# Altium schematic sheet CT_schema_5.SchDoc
size 369 x 245 mm
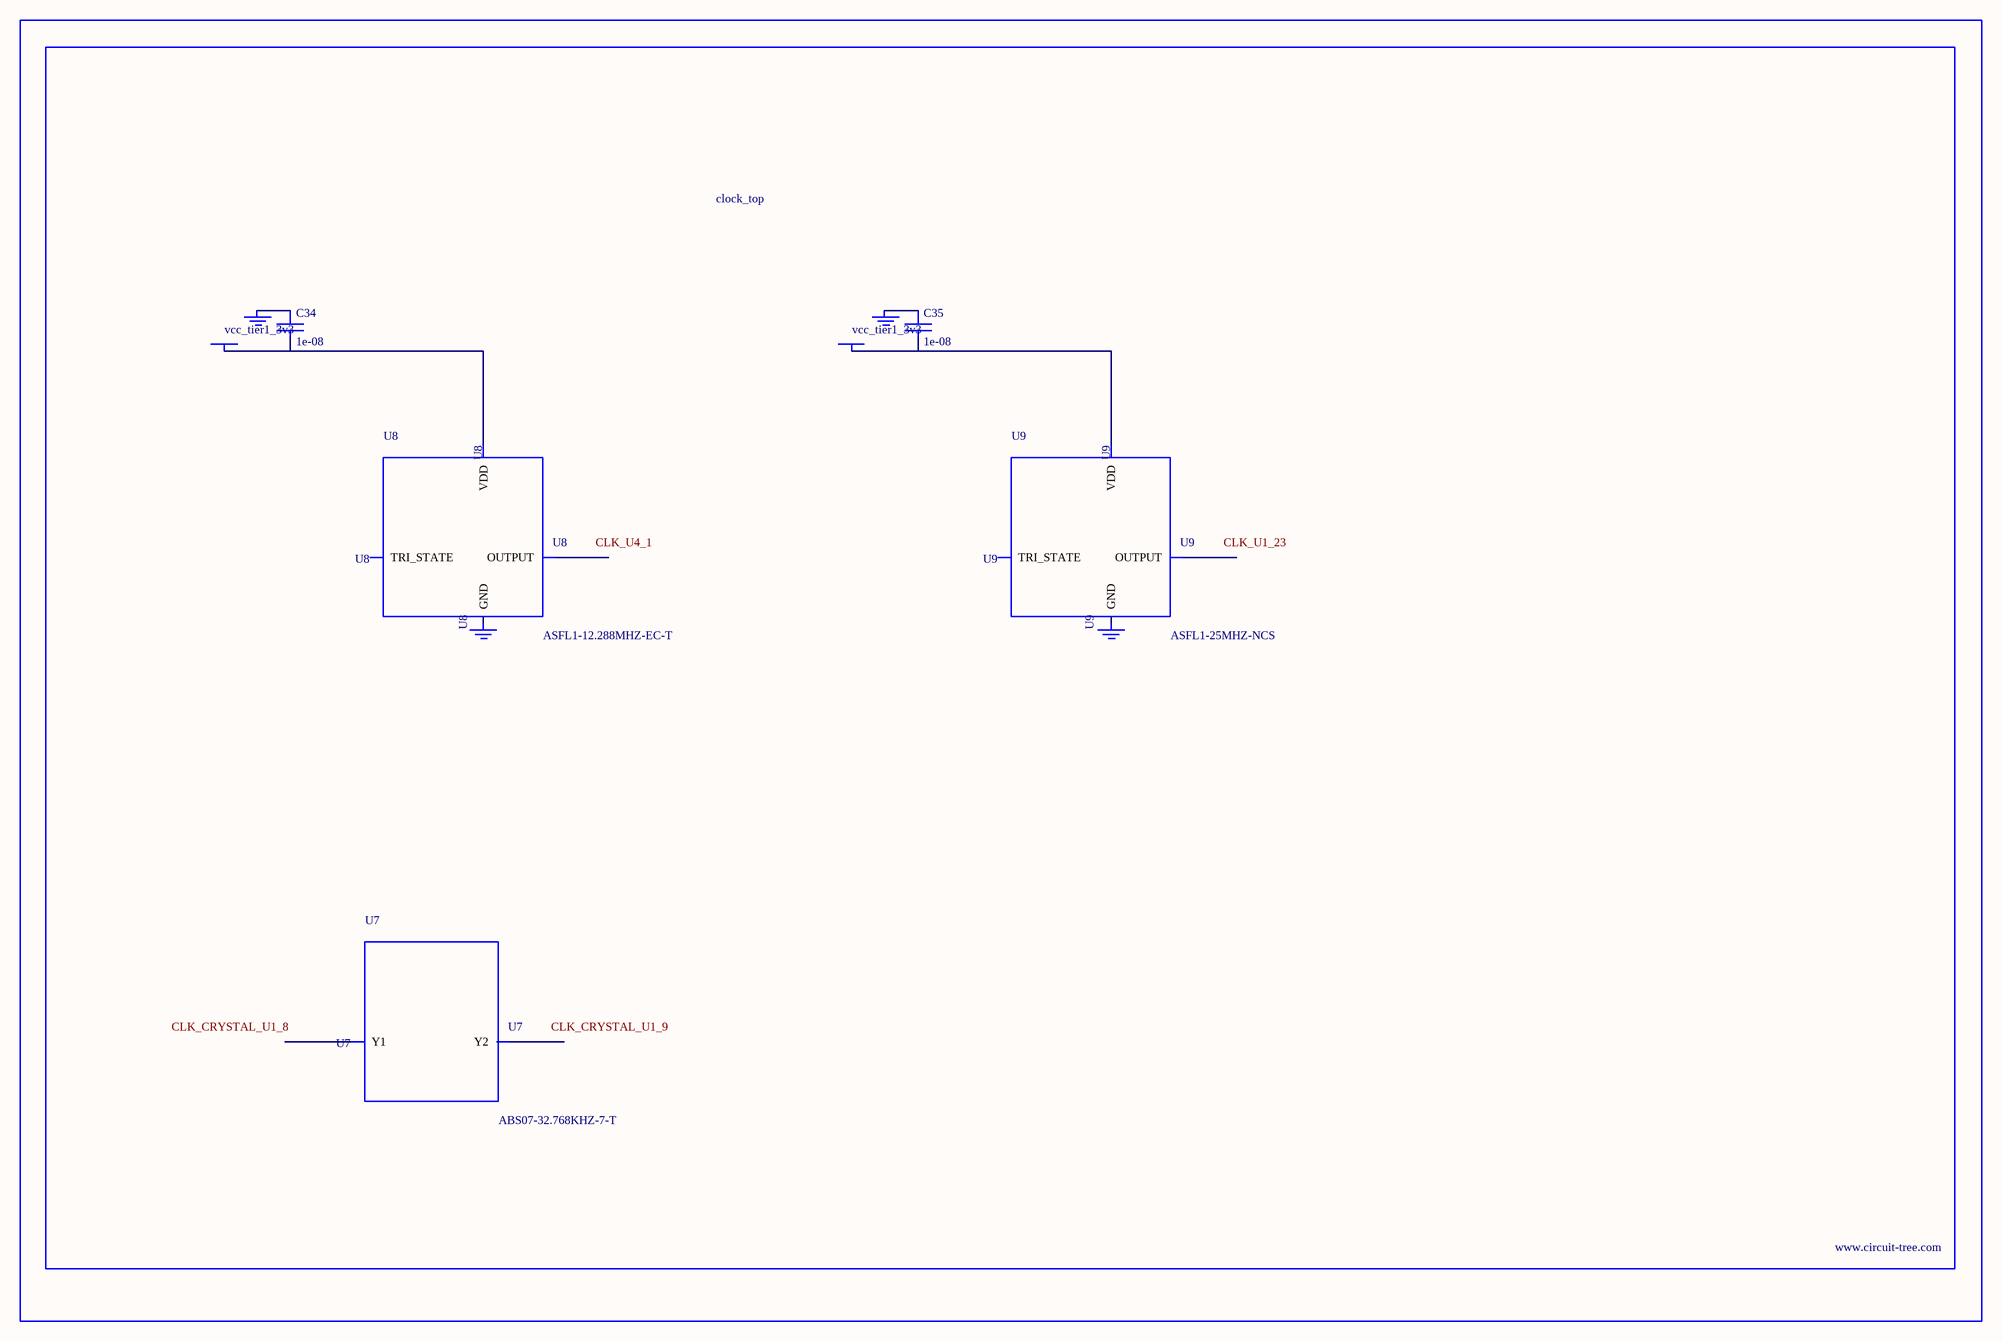
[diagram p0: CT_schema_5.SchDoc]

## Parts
BORDER4  (no value)
C34  1e-08  [C0402]
C35  1e-08  [C0402]
GND_INSTANCE_4_0  (no value)
GND_INSTANCE_4_1  (no value)
GND_INSTANCE_4_2  (no value)
GND_INSTANCE_4_3  (no value)
POWER_INSTANCE_4_0  vcc_tier1_3v3
POWER_INSTANCE_4_1  vcc_tier1_3v3
U7  ABS07-32.768KHZ-7-T  [ABS07-32.768KHZ-7-T]
U8  ASFL1-12.288MHZ-EC-T  [ASFL1]
U9  ASFL1-25MHZ-NCS  [ASFL1]

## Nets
NetC34_1: C34.1 GND_INSTANCE_4_0.0(GND)
NetC34_2: C34.2 POWER_INSTANCE_4_0.0(PWR) U8.4(VDD)
NetC35_1: C35.1 GND_INSTANCE_4_2.0(GND)
NetC35_2: C35.2 POWER_INSTANCE_4_1.0(PWR) U9.4(VDD)

Not connected (* = marked no-connect by the designer): GND_INSTANCE_4_1 0(GND); GND_INSTANCE_4_3 0(GND); U7 1(Y1) 2(Y2); U8 1(TRI_STATE) 2(GND) 3(OUTPUT); U9 1(TRI_STATE) 2(GND) 3(OUTPUT)

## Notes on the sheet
- Labels drawn without touching a wire or pin: CLK_CRYSTAL_U1_8, CLK_CRYSTAL_U1_9, CLK_U1_23, CLK_U4_1

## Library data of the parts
BORDER4 = BORDER_PAGE4
C34 C35 = C0402C103K3RAC
GND_INSTANCE_4_0-GND_INSTANCE_4_3 = GND
POWER_INSTANCE_4_0 POWER_INSTANCE_4_1 = PWR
